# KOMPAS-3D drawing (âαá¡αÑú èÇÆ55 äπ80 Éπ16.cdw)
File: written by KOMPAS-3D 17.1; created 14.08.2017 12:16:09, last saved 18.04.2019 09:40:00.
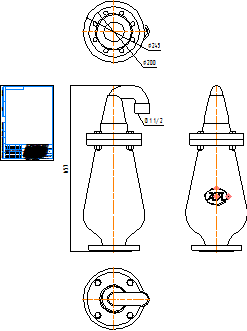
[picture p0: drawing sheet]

Sheet 1: A4, portrait

Title block, sheet 1: name: Гранрег КАТ55 Ду80 Ру16; material: Внимание! Данный продукт является объектом авторского права ООО «Торговый Дом АДЛ». / Запрещается изменение, копирование, распространение / (в том числе путем копирования на другие сайты и ресурсы в Интернете) / или любое иное использование информации и объектов без предварительного / согласия правообладателя (ООО «Торговый Дом АДЛ»).; mass: 116,3; sheets: 1; organisation: ООО "Торговый дом АДЛ"; sheet format: A4; stored path: \\adlc.lan\data\АДЛ_ПКД\3D-модели\ADL production\Клапаны КАТ ГРАНРЕГ\КАТ55\KOMPAS 2D\Гранрег КАТ55 Ду80 Ру16.cdw

Views: Вид 1, Проекционный вид 2, Проекционный вид 3, Проекционный вид 4
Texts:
  kka
  adl
Dimensions and other numbers on the sheet: 657; 245; 200; 1:1; 1; 116,3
